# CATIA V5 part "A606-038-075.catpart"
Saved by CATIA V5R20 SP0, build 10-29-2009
Part number: A606-038-075
Source: Unknown
Property "ARTICLENO": "A606-038-075"
Property "BOMINFO": "A606-038-075"
Property "CODE": "A606-038-075"
Property "HOLES": "2"
Property "L": "75.000"
Property "L1": "15.000"
Property "L2": "45.000"
Property "LINA": "A606-038-075"
Property "NB": "A606-038-075"
Property "NBSYN": "$CODE."
Property "NN": "A606"
Property "NT": "Wear Plates, self-lubricating"
Property "SCREW": "2xM6"
Property "SUPPLIER": "CF"
Property "W": "38.000"
Bounding box of the stored display mesh (mm): x -19 to 19, y -5 to 5, z -37.5 to 37.5
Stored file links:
  C:\Users\Utente\Desktop\3D files A606\A606-038-075.catpart
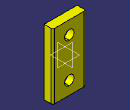
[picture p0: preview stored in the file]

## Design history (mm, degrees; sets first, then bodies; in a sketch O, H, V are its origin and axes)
Body1 "Geometry.1" (main body)
  Solid1 "A606-038-075.catpart": solid without history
